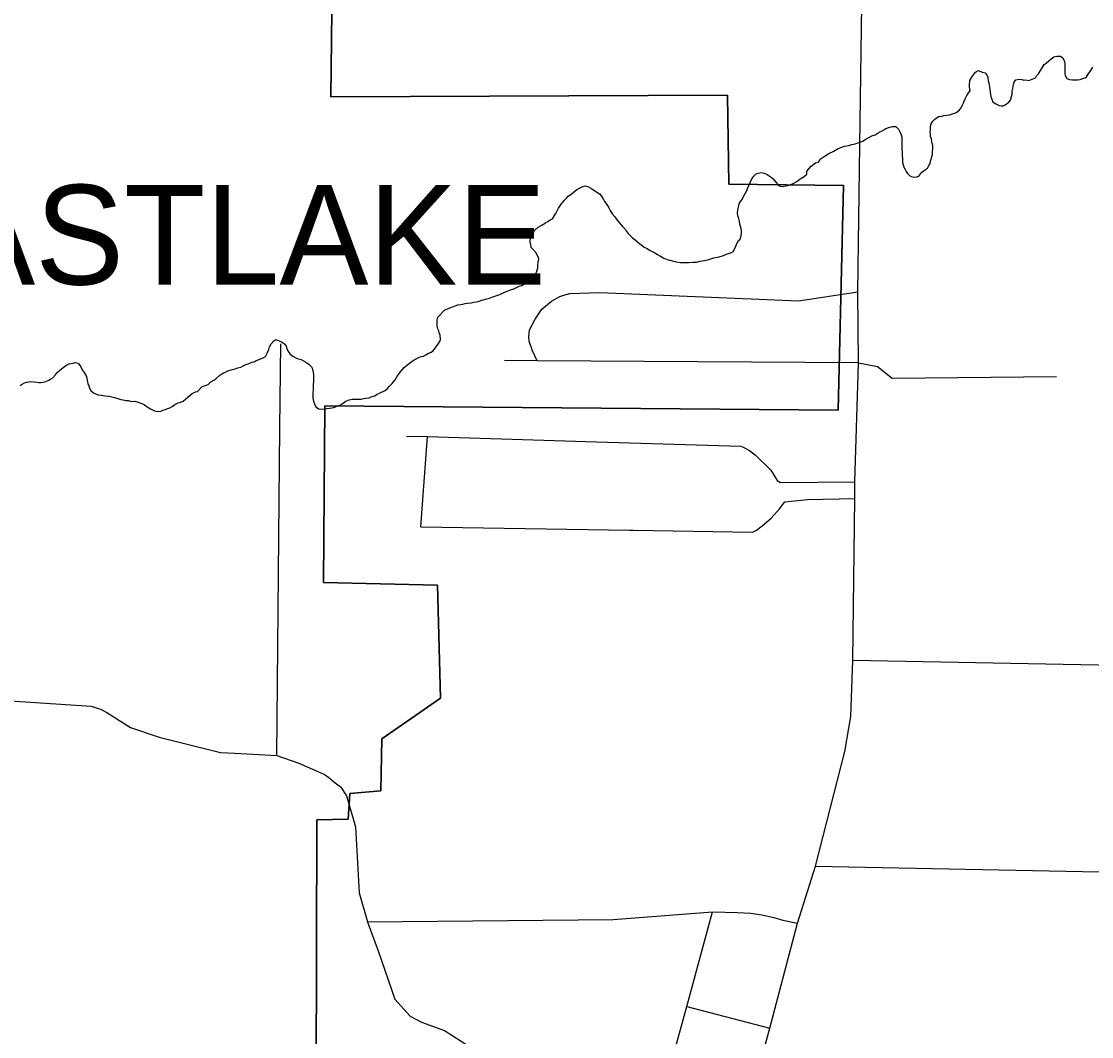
# Model space of a CAD drawing. Extents: x 0 to 34, y 0 to 22.
# Drawn here: x 5.618 to 6.635, y 16.088 to 17.053 of the extents above; entities that cross this region are included whole.
import ezdxf

# ---------------------------------------------------------------- set-up
doc = ezdxf.new("R2010")
doc.units = 0
for name, color, linetype in [('GM_X_City_Street', 7, 'Continuous'), ('GM_X_Corporation', 7, 'Continuous'), ('GM_X_Corporation_Text', 7, 'Continuous'), ('GM_X_County_Road', 7, 'Continuous'), ('GM_X_Major_River_Text', 7, 'Continuous'), ('GM_X_Minor_River', 7, 'Continuous')]:
    doc.layers.add(name, color=color, linetype=linetype)

msp = doc.modelspace()

# ---------------------------------------------------------------- linework, layer by layer
at = {"layer": 'GM_X_City_Street'}
for p, q in [((5.9974, 16.5722), (6.0037, 16.6581)), ((6.4082, 16.4454), (6.9292, 16.4354)), ((6.3726, 16.2496), (6.9055, 16.2389)), ((6.2503, 16.1162), (6.3291, 16.0956))]:
    msp.add_line(p, q, dxfattribs=at)
for points in [[(6.108, 16.7299), (6.1037, 16.7394), (6.1006, 16.7488), (6.1, 16.7526), (6.1009, 16.7595), (6.1062, 16.7698), (6.1126, 16.7793), (6.1217, 16.7869), (6.1295, 16.7913), (6.1335, 16.7925), (6.1391, 16.7939), (6.1677, 16.7949), (6.3565, 16.7871), (6.4128, 16.7957)], [(5.8606, 16.3547), (5.8636, 16.666), (5.8644, 16.7463)], [(6.4133, 16.7282), (6.108, 16.7299), (6.077, 16.7305)], [(6.4133, 16.7282), (6.4316, 16.7248), (6.4454, 16.7135), (6.6017, 16.7152)], [(5.9838, 16.6584), (6.0037, 16.6581), (6.1646, 16.6531), (6.3015, 16.6488), (6.3045, 16.6476), (6.31, 16.6447), (6.3157, 16.6404), (6.33, 16.6262), (6.3363, 16.6163), (6.3392, 16.6142), (6.41, 16.6151)], [(6.1997, 16.5689), (6.3127, 16.5671), (6.3165, 16.569), (6.322, 16.573), (6.3306, 16.5805), (6.3384, 16.5893), (6.3433, 16.5961), (6.3649, 16.5982), (6.41, 16.5991)], [(5.9974, 16.5722), (6.1957, 16.569), (6.1997, 16.5689)], [(5.9468, 16.1968), (6.1802, 16.1989), (6.2747, 16.2061), (6.2984, 16.2056), (6.3111, 16.2048), (6.3216, 16.2032), (6.3329, 16.2009), (6.3417, 16.1983), (6.3556, 16.1955)], [(6.1801, 15.8942), (6.2384, 16.0724), (6.2503, 16.1162), (6.2747, 16.2061)]]:
    msp.add_lwpolyline(points, dxfattribs=at)
at = {"layer": 'GM_X_Corporation'}
for points in [[(5.9278, 18.3408), (5.912, 16.9809), (6.2889, 16.9827), (6.2902, 16.898), (6.3993, 16.8966), (6.3942, 16.683), (5.9062, 16.6871), (5.905, 16.5193), (6.0133, 16.5167), (6.0161, 16.4093), (5.9603, 16.3708), (5.9595, 16.3211), (5.93, 16.3187), (5.9284, 16.2943), (5.8985, 16.2935), (5.8973, 15.8014)], [(5.8973, 15.8014), (5.8985, 16.2935), (5.9284, 16.2943), (5.93, 16.3187), (5.9595, 16.3211), (5.9603, 16.3708), (6.0161, 16.4093), (6.0133, 16.5167), (5.905, 16.5193), (5.9062, 16.6871), (6.3942, 16.683), (6.3993, 16.8966), (6.2902, 16.898), (6.2889, 16.9827), (5.912, 16.9809), (5.9278, 18.3408)]]:
    msp.add_lwpolyline(points, dxfattribs=at)
at = {"layer": 'GM_X_County_Road'}
for points in [[(6.413, 16.7169), (6.4133, 16.7282), (6.4128, 16.7957), (6.4148, 16.9351), (6.4201, 17.3135)], [(6.2745, 15.8939), (6.2843, 15.93), (6.3291, 16.0956), (6.3556, 16.1955), (6.3726, 16.2496), (6.4004, 16.3586), (6.4061, 16.392), (6.4082, 16.4454), (6.41, 16.5991), (6.41, 16.6151), (6.413, 16.7169)], [(5.5057, 16.4135), (5.6841, 16.4018), (5.6872, 16.4009), (5.6931, 16.3987), (5.6991, 16.3958), (5.7052, 16.392), (5.7217, 16.3813), (5.7488, 16.3723), (5.802, 16.359), (5.8067, 16.3578), (5.8206, 16.357)], [(5.8206, 16.357), (5.8606, 16.3547), (5.8815, 16.3475), (5.9025, 16.3383), (5.9056, 16.337), (5.9101, 16.3338), (5.9162, 16.3287), (5.9198, 16.326)], [(5.9198, 16.326), (5.9216, 16.3247), (5.9269, 16.3165), (5.9354, 16.287), (5.9389, 16.2241), (5.9468, 16.1968), (5.9474, 16.1946), (5.957, 16.169), (5.9729, 16.123), (5.9873, 16.1071), (5.9982, 16.1013), (6.0199, 16.0934), (6.0437, 16.0782), (6.0604, 16.0644), (6.0777, 16.0398), (6.103, 15.9957), (6.1102, 15.9733), (6.1276, 15.9392), (6.1471, 15.9146), (6.1601, 15.9023), (6.1801, 15.8942), (6.2696, 15.8759)]]:
    msp.add_lwpolyline(points, dxfattribs=at)
at = {"layer": 'GM_X_Minor_River'}
for points in [[(6.4977, 16.9636), (6.5, 16.964), (6.5027, 16.9648), (6.5049, 16.9656), (6.5068, 16.9664), (6.5094, 16.9687), (6.5109, 16.9706), (6.5121, 16.9729), (6.5132, 16.9752), (6.5146, 16.9786), (6.5165, 16.9824), (6.5184, 16.9851), (6.5195, 16.987), (6.5191, 16.9901), (6.5191, 16.992), (6.5194, 16.9965), (6.5216, 17.0004), (6.5246, 17.0046), (6.5276, 17.0061), (6.5311, 17.0046), (6.5337, 17.0039), (6.5356, 17.0013), (6.5364, 16.9994), (6.5368, 16.9963), (6.5372, 16.9944), (6.5376, 16.9921), (6.538, 16.9903), (6.5389, 16.9834), (6.5393, 16.9815), (6.5401, 16.9789), (6.5412, 16.9762), (6.5432, 16.9747), (6.5451, 16.9736), (6.547, 16.9728), (6.5489, 16.9725), (6.5508, 16.9725), (6.553, 16.9733), (6.5564, 16.976), (6.5579, 16.9779), (6.5587, 16.9802), (6.5594, 16.9836), (6.5594, 16.9863), (6.5601, 16.9889), (6.5604, 16.9909), (6.5608, 16.9928), (6.5615, 16.9951), (6.563, 16.9973), (6.5664, 16.9978), (6.5687, 16.9974), (6.5706, 16.997), (6.5725, 16.9971), (6.5752, 16.9967), (6.5816, 16.9991), (6.5827, 17.001), (6.5846, 17.0029), (6.5865, 17.006), (6.5879, 17.0086), (6.5898, 17.0117), (6.5917, 17.0132), (6.5943, 17.0152), (6.5966, 17.0171), (6.5992, 17.019), (6.6019, 17.0198), (6.6053, 17.0198), (6.6076, 17.018), (6.6091, 17.0145), (6.6095, 17.0123), (6.6096, 17.01), (6.6096, 17.0081), (6.6096, 17.0062), (6.6096, 17.0031), (6.61, 17.0012), (6.6116, 16.9986), (6.6139, 16.9975), (6.6169, 16.9971), (6.6192, 16.9971), (6.6215, 16.9972), (6.6241, 16.9976), (6.6268, 16.9984), (6.6298, 16.9995), (6.6317, 17.0026), (6.6343, 17.006), (6.6361, 17.0091)], [(6.3028, 16.8833), (6.3043, 16.8864), (6.3058, 16.889), (6.3072, 16.8921), (6.308, 16.894), (6.3091, 16.8967), (6.3106, 16.8997), (6.312, 16.9032), (6.3139, 16.9055), (6.3162, 16.9078), (6.3181, 16.9086), (6.3211, 16.909), (6.3238, 16.9086), (6.3268, 16.9071), (6.3287, 16.906), (6.3306, 16.9045), (6.3325, 16.903), (6.3349, 16.9), (6.3372, 16.8973), (6.3391, 16.8962), (6.3417, 16.8959), (6.3444, 16.8963), (6.3463, 16.8967), (6.3485, 16.8974), (6.3519, 16.899), (6.355, 16.9005), (6.358, 16.9032), (6.3617, 16.9052), (6.3644, 16.9075), (6.3643, 16.9105), (6.3685, 16.9151), (6.3726, 16.9182), (6.3753, 16.919), (6.3771, 16.9217), (6.3809, 16.9244), (6.3854, 16.9271), (6.3899, 16.9294), (6.3941, 16.9318), (6.3975, 16.9333), (6.4001, 16.9341), (6.4024, 16.9345), (6.4043, 16.9349), (6.407, 16.9357), (6.4104, 16.9365), (6.4157, 16.9381), (6.4175, 16.9388), (6.4198, 16.9404), (6.4262, 16.9439), (6.4292, 16.945), (6.4311, 16.9462), (6.433, 16.9474), (6.4353, 16.9485), (6.4375, 16.9497), (6.4394, 16.9508), (6.4424, 16.952), (6.4459, 16.9528), (6.4489, 16.9528), (6.4516, 16.9502), (6.4531, 16.9472), (6.4539, 16.9449), (6.4547, 16.9426), (6.4548, 16.9339), (6.4548, 16.9312), (6.4549, 16.9282), (6.4549, 16.9255), (6.4553, 16.9221), (6.4553, 16.9187), (6.4565, 16.9141), (6.4577, 16.9118), (6.4589, 16.9099), (6.46, 16.9081), (6.4623, 16.9058), (6.4654, 16.9047), (6.4688, 16.9051), (6.4707, 16.9055), (6.4737, 16.9093), (6.4771, 16.912), (6.4789, 16.9132), (6.4804, 16.9159), (6.4815, 16.9178), (6.4823, 16.9208), (6.483, 16.9239), (6.4837, 16.9262), (6.4837, 16.9285), (6.484, 16.9323), (6.484, 16.9349), (6.4836, 16.9368), (6.4832, 16.9387), (6.4828, 16.941), (6.482, 16.9433), (6.482, 16.9459), (6.4816, 16.9478), (6.4819, 16.9497), (6.4819, 16.9524), (6.4826, 16.9555), (6.4841, 16.9578), (6.486, 16.9597), (6.4894, 16.9624), (6.4928, 16.9628), (6.4947, 16.9632), (6.4977, 16.9636)], [(6.1088, 16.8213), (6.1091, 16.8239), (6.1095, 16.8266), (6.1087, 16.8296), (6.1067, 16.833), (6.104, 16.8361), (6.1025, 16.8379), (6.1021, 16.8402), (6.1013, 16.8433), (6.1016, 16.8474), (6.1031, 16.8501), (6.1046, 16.8524), (6.1057, 16.8543), (6.1091, 16.857), (6.1118, 16.8586), (6.1159, 16.8613), (6.1182, 16.8624), (6.1204, 16.864), (6.1227, 16.8652), (6.1246, 16.8682), (6.1257, 16.8701), (6.1272, 16.8728), (6.1283, 16.8751), (6.1309, 16.8789), (6.1324, 16.8809), (6.1339, 16.8828), (6.1358, 16.8847), (6.1376, 16.8866), (6.1399, 16.8882), (6.1418, 16.8897), (6.1437, 16.8912), (6.1459, 16.8928), (6.1482, 16.8943), (6.1508, 16.8955), (6.1538, 16.8963), (6.1569, 16.8956), (6.1592, 16.8941), (6.1615, 16.8926), (6.1649, 16.8903), (6.1672, 16.8888), (6.1691, 16.8865), (6.1711, 16.8835), (6.1722, 16.8816), (6.1742, 16.8786), (6.1761, 16.8756), (6.1773, 16.8729), (6.1792, 16.8699), (6.1819, 16.8669), (6.1842, 16.8639), (6.1857, 16.862), (6.1888, 16.8582), (6.1919, 16.8548), (6.193, 16.8529), (6.1946, 16.851), (6.1965, 16.8491), (6.1988, 16.8469), (6.2011, 16.845), (6.2034, 16.8431), (6.2057, 16.8412), (6.208, 16.8397), (6.2099, 16.8382), (6.2126, 16.8367), (6.2149, 16.8352), (6.2172, 16.8341), (6.2198, 16.8326), (6.2225, 16.8311), (6.2252, 16.8296), (6.2286, 16.8278), (6.2317, 16.8263), (6.2401, 16.8241), (6.2442, 16.8234), (6.248, 16.8234), (6.2522, 16.8234), (6.256, 16.8239), (6.2594, 16.8239), (6.2628, 16.8247), (6.267, 16.8255), (6.2712, 16.8263), (6.2761, 16.8279), (6.281, 16.829), (6.2852, 16.8302), (6.2886, 16.8318), (6.292, 16.8326), (6.2942, 16.8341), (6.2961, 16.8376), (6.2976, 16.8406), (6.299, 16.8441), (6.3009, 16.8456), (6.302, 16.849), (6.3024, 16.8517), (6.3023, 16.854), (6.3016, 16.857), (6.3008, 16.8601), (6.3004, 16.8627), (6.2996, 16.8654), (6.2988, 16.868), (6.2984, 16.8707), (6.2987, 16.8734), (6.2994, 16.876), (6.3005, 16.8802), (6.3028, 16.8833)], [(5.8955, 16.7164), (5.8955, 16.7138), (5.8955, 16.7115), (5.8952, 16.7062), (5.8952, 16.7039), (5.8953, 16.702), (5.8949, 16.7001), (5.8949, 16.6966), (5.895, 16.6947), (5.8954, 16.6917), (5.8966, 16.6883), (5.8981, 16.686), (5.9004, 16.6845), (5.9038, 16.6842), (5.908, 16.6846), (5.9106, 16.685), (5.9129, 16.6854), (5.9148, 16.6858), (5.9171, 16.6866), (5.9205, 16.6878), (5.9227, 16.6893), (5.9261, 16.6916), (5.9295, 16.6928), (5.9326, 16.6936), (5.936, 16.6936), (5.939, 16.6937), (5.9409, 16.6937), (5.9432, 16.6941), (5.9454, 16.6945), (5.9485, 16.6949), (5.9504, 16.6957), (5.9538, 16.6968), (5.956, 16.6984), (5.9587, 16.6996), (5.9636, 16.7019), (5.9655, 16.7034), (5.9677, 16.7061), (5.9703, 16.7084), (5.973, 16.7119), (5.9748, 16.7149), (5.9778, 16.7191), (5.9816, 16.7237), (5.9853, 16.7268), (5.988, 16.7288), (5.9902, 16.7303), (5.9929, 16.7318), (5.9959, 16.7334), (5.9981, 16.7342), (6, 16.7346), (6.0023, 16.7357), (6.0049, 16.7373), (6.0068, 16.7381), (6.0091, 16.7396), (6.0117, 16.7431), (6.0143, 16.7465), (6.0154, 16.7484), (6.0162, 16.7503), (6.0158, 16.7545), (6.015, 16.7568), (6.0146, 16.7587), (6.0138, 16.7606), (6.013, 16.7629), (6.013, 16.7671), (6.0129, 16.769), (6.0137, 16.7716), (6.0204, 16.7785), (6.0223, 16.7793), (6.025, 16.7805), (6.0284, 16.7817), (6.0302, 16.7824), (6.0325, 16.7832), (6.0355, 16.7836), (6.0374, 16.784), (6.0397, 16.7844), (6.0416, 16.7848), (6.0454, 16.7853), (6.048, 16.7857), (6.0507, 16.7861), (6.053, 16.7869), (6.0556, 16.7876), (6.059, 16.7888), (6.0628, 16.7896), (6.0658, 16.7908), (6.0696, 16.792), (6.0726, 16.7931), (6.0757, 16.7947), (6.0794, 16.7962), (6.0828, 16.7974), (6.0859, 16.7986), (6.0885, 16.7998), (6.0911, 16.8009), (6.0934, 16.8017), (6.0953, 16.8029), (6.0972, 16.8036), (6.0998, 16.806), (6.1017, 16.8079), (6.1036, 16.8094), (6.1062, 16.8117), (6.1073, 16.8144), (6.1088, 16.8186), (6.1088, 16.8213)], [(5.6537, 16.7205), (5.6563, 16.7228), (5.66, 16.7255), (5.6631, 16.7271), (5.665, 16.7275), (5.6672, 16.7279), (5.6691, 16.7283), (5.6718, 16.7279), (5.6745, 16.7242), (5.6757, 16.7215), (5.6776, 16.7189), (5.6795, 16.7158), (5.6799, 16.7139), (5.6803, 16.7113), (5.6811, 16.7086), (5.6819, 16.7063), (5.6827, 16.7041), (5.6838, 16.7018), (5.6865, 16.6995), (5.6884, 16.6988), (5.6907, 16.6977), (5.6938, 16.6973), (5.6976, 16.6966), (5.701, 16.6963), (5.7037, 16.6959), (5.7063, 16.6952), (5.7094, 16.6941), (5.7124, 16.6933), (5.7147, 16.693), (5.717, 16.6922), (5.7193, 16.6923), (5.7227, 16.6915), (5.7257, 16.6916), (5.7288, 16.6908), (5.733, 16.6893), (5.7349, 16.6882), (5.7375, 16.6863), (5.7406, 16.6845), (5.7425, 16.6834), (5.7444, 16.6826), (5.7475, 16.6819), (5.7505, 16.6823), (5.7524, 16.6831), (5.7546, 16.6839), (5.7569, 16.6846), (5.7588, 16.6854), (5.7611, 16.6866), (5.7637, 16.6885), (5.7667, 16.6901), (5.7694, 16.6908), (5.7716, 16.6916), (5.7765, 16.6959), (5.7803, 16.6989), (5.7833, 16.7005), (5.7852, 16.7009), (5.7897, 16.7055), (5.7954, 16.7075), (5.798, 16.7101), (5.8006, 16.7117), (5.8025, 16.7129), (5.8063, 16.7163), (5.8093, 16.7182), (5.8112, 16.719), (5.8142, 16.7206), (5.8172, 16.7214), (5.821, 16.7225), (5.8237, 16.7233), (5.8263, 16.7241), (5.8286, 16.7253), (5.8312, 16.7265), (5.8342, 16.7276), (5.8369, 16.7288), (5.8392, 16.7292), (5.841, 16.7304), (5.8429, 16.7311), (5.8452, 16.7319), (5.8471, 16.7327), (5.8497, 16.7342), (5.8516, 16.7381), (5.8531, 16.7407), (5.8538, 16.7434), (5.8553, 16.7461), (5.8579, 16.7492), (5.8598, 16.7503), (5.8628, 16.7492), (5.8651, 16.7481), (5.8678, 16.7462), (5.8694, 16.744), (5.8701, 16.7417), (5.8713, 16.739), (5.8732, 16.7364), (5.8759, 16.7345), (5.8786, 16.733), (5.8809, 16.7319), (5.8839, 16.7312), (5.8881, 16.7289), (5.8912, 16.7267), (5.8939, 16.724), (5.895, 16.721), (5.8951, 16.7191), (5.8955, 16.7164)], [(5.6166, 16.7065), (5.6185, 16.708), (5.6208, 16.7092), (5.623, 16.7096), (5.6249, 16.71), (5.6268, 16.7104), (5.6299, 16.71), (5.6325, 16.7097), (5.6344, 16.7093), (5.6363, 16.7093), (5.6386, 16.7097), (5.6412, 16.7105), (5.6439, 16.7117), (5.6458, 16.7128), (5.6477, 16.714), (5.6503, 16.7167), (5.6518, 16.719), (5.6537, 16.7205)]]:
    msp.add_lwpolyline(points, dxfattribs=at)

# ---------------------------------------------------------------- texts
at = {"layer": 'GM_X_Corporation_Text'}
msp.add_text('EASTLAKE', height=0.0947, rotation=0, dxfattribs=at).set_placement((5.462, 16.8026))
at = {"layer": 'GM_X_Major_River_Text'}
msp.add_text('Chagrin', height=0.09477, rotation=305.9502, dxfattribs=at).set_placement((5.4157, 16.2318))

doc.saveas('drawing.dxf')
